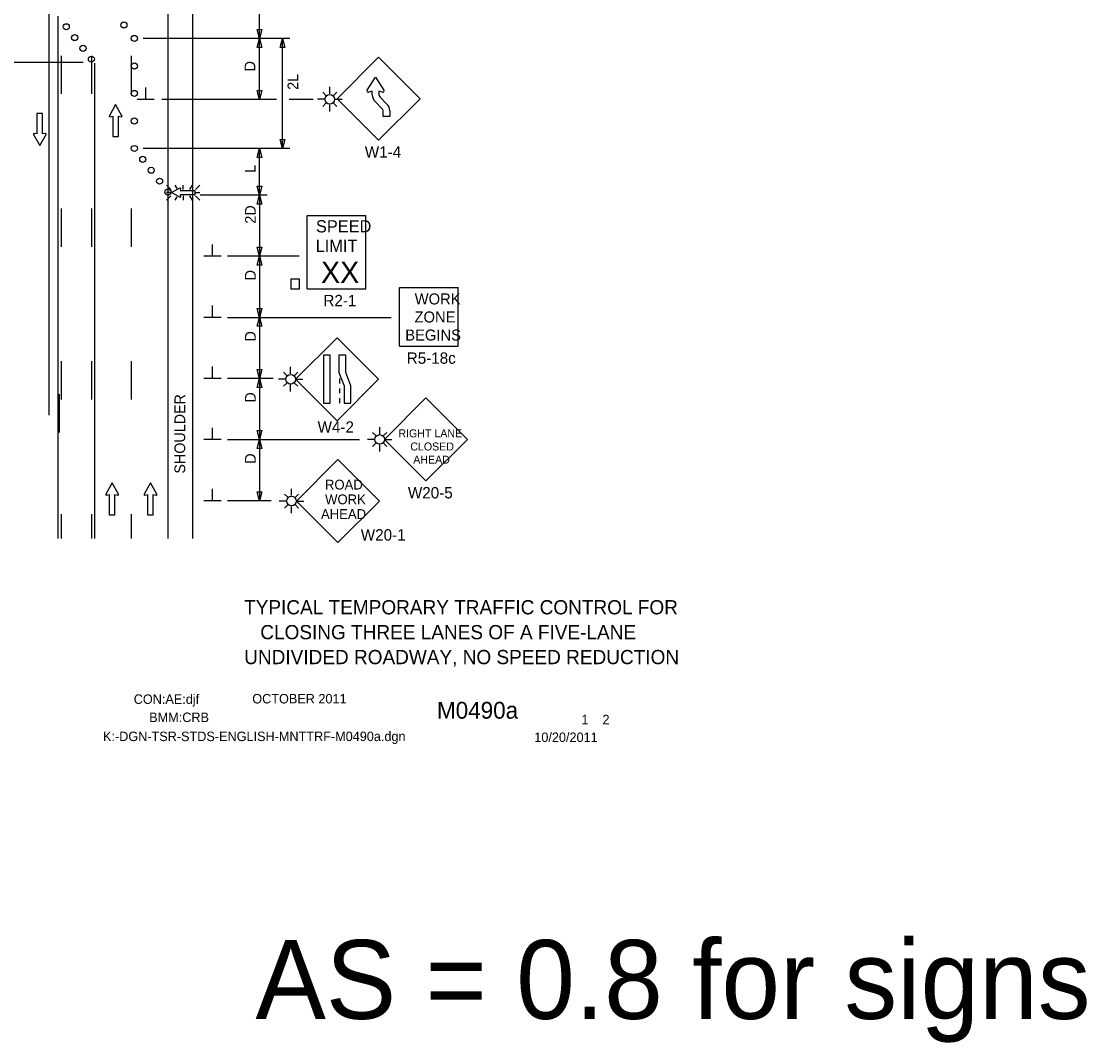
# Model space of a CAD drawing. Extents: x 16399 to 18476, y 7023 to 8321.
# Drawn here: x 17017 to 17715, y 7023 to 7691 of the extents above; entities that cross this region are included whole.
import ezdxf

# ---------------------------------------------------------------- set-up
doc = ezdxf.new("R2010")
doc.units = 0
for name, color, linetype in [('ALI_LEGAL_EX', 7, 'Continuous'), ('BORDER', 7, 'Continuous'), ('BORDER_SIGNAL_WO', 7, 'Continuous'), ('MT_SCRATCH_LEVEL_E', 7, 'Continuous'), ('PAVT_EDGE_EX', 7, 'Continuous'), ('TRAFFIC_SIGNS_PR', 7, 'Continuous'), ('TYPICAL_TEXT_DIMEN_PR', 7, 'Continuous')]:
    doc.layers.add(name, color=color, linetype=linetype)

msp = doc.modelspace()

# ---------------------------------------------------------------- linework, layer by layer
at = {"layer": 'ALI_LEGAL_EX'}
for points in [[(17043.08, 7668.47), (17043.08, 7643.47)], [(17063.08, 7668.47), (17063.08, 7643.47)], [(17089.08, 7668.47), (17089.08, 7643.47)], [(17043.08, 7568.47), (17043.08, 7543.47)], [(17063.08, 7568.47), (17063.08, 7543.47)], [(17089.08, 7568.47), (17089.08, 7543.47)], [(17043.08, 7468.47), (17043.08, 7443.47)], [(17063.08, 7468.47), (17063.08, 7443.47)], [(17089.08, 7468.47), (17089.08, 7443.47)], [(17043.08, 7368.47), (17043.08, 7352.54)], [(17063.08, 7368.47), (17063.08, 7352.54)], [(17089.08, 7368.47), (17089.08, 7352.54)]]:
    msp.add_lwpolyline(points, dxfattribs=at)
at = {"layer": 'BORDER'}
msp.add_line((17289.25, 7291.25), (17289.25, 7291.25), dxfattribs=at)
at = {"layer": 'MT_SCRATCH_LEVEL_E'}
for p, q in [((17031.01, 7630.57), (17027.26, 7630.57)), ((17027.26, 7630.57), (17027.26, 7617.31)), ((17031.01, 7630.57), (17027.26, 7630.57)), ((17027.26, 7630.57), (17027.26, 7617.31)), ((17031.01, 7617.31), (17031.01, 7630.57)), ((17031.01, 7617.31), (17031.01, 7630.57)), ((17078.82, 7636.46), (17074.71, 7629.22)), ((17078.82, 7636.46), (17074.71, 7629.22)), ((17082.97, 7629.22), (17078.82, 7636.46)), ((17082.97, 7629.22), (17078.82, 7636.46)), ((17075.19, 7628.54), (17076.97, 7628.86)), ((17075.19, 7628.54), (17076.97, 7628.86)), ((17076.97, 7628.86), (17076.97, 7615.6)), ((17076.97, 7628.86), (17076.97, 7615.6)), ((17080.71, 7615.6), (17080.71, 7628.86)), ((17080.71, 7628.86), (17082.49, 7628.54)), ((17080.71, 7615.6), (17080.71, 7628.86)), ((17080.71, 7628.86), (17082.49, 7628.54)), ((17025.01, 7616.94), (17029.15, 7609.7)), ((17025.01, 7616.94), (17029.15, 7609.7)), ((17027.26, 7617.31), (17025.49, 7617.63)), ((17027.26, 7617.31), (17025.49, 7617.63)), ((17029.15, 7609.7), (17033.27, 7616.94)), ((17029.15, 7609.7), (17033.27, 7616.94)), ((17032.78, 7617.63), (17031.01, 7617.31)), ((17032.78, 7617.63), (17031.01, 7617.31)), ((17076.97, 7615.6), (17080.71, 7615.6)), ((17076.97, 7615.6), (17080.71, 7615.6)), ((17076.52, 7388.88), (17072.41, 7381.64)), ((17076.52, 7388.88), (17072.41, 7381.64)), ((17080.67, 7381.64), (17076.52, 7388.88)), ((17080.67, 7381.64), (17076.52, 7388.88)), ((17101.61, 7388.88), (17097.5, 7381.64)), ((17101.61, 7388.88), (17097.5, 7381.64)), ((17105.75, 7381.64), (17101.61, 7388.88)), ((17105.75, 7381.64), (17101.61, 7388.88)), ((17072.89, 7380.95), (17074.67, 7381.27)), ((17072.89, 7380.95), (17074.67, 7381.27)), ((17074.67, 7381.27), (17074.67, 7368.01)), ((17074.67, 7381.27), (17074.67, 7368.01)), ((17078.41, 7368.01), (17078.41, 7381.27)), ((17078.41, 7381.27), (17080.19, 7380.95)), ((17078.41, 7368.01), (17078.41, 7381.27)), ((17078.41, 7381.27), (17080.19, 7380.95)), ((17097.98, 7380.95), (17099.76, 7381.27)), ((17097.98, 7380.95), (17099.76, 7381.27)), ((17099.76, 7381.27), (17099.76, 7368.01)), ((17099.76, 7381.27), (17099.76, 7368.01)), ((17103.5, 7368.01), (17103.5, 7381.27)), ((17103.5, 7381.27), (17105.28, 7380.95)), ((17103.5, 7368.01), (17103.5, 7381.27)), ((17103.5, 7381.27), (17105.28, 7380.95)), ((17074.67, 7368.01), (17078.41, 7368.01)), ((17074.67, 7368.01), (17078.41, 7368.01)), ((17099.76, 7368.01), (17103.5, 7368.01)), ((17099.76, 7368.01), (17103.5, 7368.01))]:
    msp.add_line(p, q, dxfattribs=at)
for centre, start, end in [((17075.11, 7629), 150.42484, 279.96381), ((17075.11, 7629), 150.42484, 279.96381), ((17082.56, 7629), 260.03619, 29.77312), ((17082.56, 7629), 260.03619, 29.77312), ((17025.42, 7617.17), 80.03619, 209.77312), ((17025.42, 7617.17), 80.03619, 209.77312), ((17032.86, 7617.17), 330.42484, 99.96381), ((17032.86, 7617.17), 330.42484, 99.96381), ((17072.81, 7381.41), 150.42484, 279.96381), ((17072.81, 7381.41), 150.42484, 279.96381), ((17080.26, 7381.42), 260.03619, 29.77312), ((17080.26, 7381.42), 260.03619, 29.77312), ((17097.9, 7381.41), 150.42484, 279.96381), ((17097.9, 7381.41), 150.42484, 279.96381), ((17105.34, 7381.42), 260.03619, 29.77312), ((17105.34, 7381.42), 260.03619, 29.77312)]:
    msp.add_arc(centre, 0.463, start, end, dxfattribs=at)
at = {"layer": 'PAVT_EDGE_EX'}
for p, q in [((17035.15, 8262.34), (17035.15, 7433.15)), ((17113.08, 8207.29), (17113.08, 7352.54)), ((17129.08, 8207.29), (17129.08, 7352.54)), ((17041.08, 7694.36), (17041.08, 7352.54)), ((17065.08, 7663.49), (17065.08, 7352.54))]:
    msp.add_line(p, q, dxfattribs=at)
msp.add_lwpolyline([(17042.08, 7421.93), (17042.08, 7446.93)], dxfattribs=at)
at = {"layer": 'TRAFFIC_SIGNS_PR'}
for p, q in [((17223.81, 7640.31), (17250.97, 7667.46)), ((17278.12, 7640.31), (17250.97, 7667.46)), ((17216.52, 7642.45), (17214.42, 7644.56)), ((17219.04, 7643.5), (17219.04, 7648)), ((17221.55, 7642.45), (17223.66, 7644.56)), ((17215.88, 7639.94), (17211.05, 7639.94)), ((17222.19, 7639.94), (17227.07, 7639.94)), ((17250.97, 7613.16), (17223.81, 7640.31)), ((17253.38, 7633.79), (17248.67, 7638.51)), ((17253.38, 7633.79), (17248.67, 7638.51)), ((17278.12, 7640.31), (17250.97, 7613.16)), ((17256.44, 7636.85), (17251.72, 7641.56)), ((17251.72, 7641.56), (17256.44, 7636.85)), ((17216.52, 7637.43), (17214.42, 7635.32)), ((17219.04, 7631.98), (17219.04, 7636.39)), ((17221.55, 7637.43), (17223.66, 7635.32)), ((17112.21, 7583.72), (17115.03, 7580.9)), ((17117.65, 7583.72), (17118.85, 7581.63)), ((17123.12, 7580.9), (17123.12, 7583.72)), ((17128.9, 7583.72), (17127.28, 7580.9)), ((17131.2, 7580.9), (17134.02, 7583.72)), ((17115.03, 7578.87), (17112.21, 7578.87)), ((17112.21, 7574.02), (17115.03, 7576.84)), ((17118.93, 7576.2), (17117.67, 7574.02)), ((17123.12, 7576.84), (17123.12, 7574.02)), ((17127.25, 7576.84), (17128.88, 7574.02)), ((17131.2, 7578.87), (17134.02, 7578.87)), ((17131.2, 7576.84), (17134.02, 7574.02)), ((17204.2, 7563.98), (17242.6, 7563.98)), ((17204.2, 7515.98), (17204.2, 7563.98)), ((17242.6, 7515.98), (17242.6, 7563.98)), ((17204.2, 7515.98), (17242.6, 7515.98)), ((17264.63, 7478.32), (17264.63, 7516.72)), ((17264.63, 7516.72), (17303.03, 7516.72)), ((17303.03, 7478.32), (17303.03, 7516.72)), ((17223.76, 7483.84), (17196.61, 7456.69)), ((17250.92, 7456.69), (17223.76, 7483.84)), ((17264.63, 7478.32), (17303.03, 7478.32)), ((17193.4, 7460.31), (17193.4, 7464.81)), ((17190.24, 7456.75), (17185.4, 7456.75)), ((17190.88, 7459.26), (17188.77, 7461.37)), ((17195.91, 7459.26), (17198.02, 7461.37)), ((17196.55, 7456.75), (17201.43, 7456.75)), ((17196.61, 7456.69), (17223.76, 7429.54)), ((17223.76, 7429.54), (17250.92, 7456.69)), ((17225.4, 7457.18), (17225.4, 7453.98)), ((17190.88, 7454.24), (17188.77, 7452.13)), ((17193.4, 7448.78), (17193.4, 7453.2)), ((17195.91, 7454.24), (17198.02, 7452.13)), ((17225.4, 7450.78), (17225.4, 7447.58)), ((17225.4, 7444.38), (17225.4, 7441.18)), ((17282.02, 7444.5), (17254.87, 7417.35)), ((17309.17, 7417.35), (17282.02, 7444.5)), ((17249.2, 7419.86), (17247.09, 7421.97)), ((17251.71, 7420.9), (17251.71, 7425.41)), ((17254.23, 7419.86), (17256.33, 7421.97)), ((17248.56, 7417.35), (17243.72, 7417.35)), ((17249.2, 7414.84), (17247.09, 7412.73)), ((17254.23, 7414.84), (17256.33, 7412.73)), ((17254.87, 7417.35), (17259.75, 7417.35)), ((17254.87, 7417.35), (17282.02, 7390.2)), ((17282.02, 7390.2), (17309.17, 7417.35)), ((17251.71, 7409.38), (17251.71, 7413.8)), ((17224.33, 7404.21), (17197.15, 7377.02)), ((17251.52, 7377.02), (17224.33, 7404.21)), ((17191.48, 7379.53), (17189.37, 7381.64)), ((17193.99, 7380.57), (17193.99, 7385.08)), ((17196.51, 7379.53), (17198.61, 7381.64)), ((17190.84, 7377.02), (17186, 7377.02)), ((17191.48, 7374.51), (17189.37, 7372.4)), ((17193.99, 7369.05), (17193.99, 7373.47)), ((17196.51, 7374.51), (17198.61, 7372.4)), ((17197.15, 7377.02), (17202.03, 7377.02)), ((17197.15, 7377.02), (17224.33, 7349.83)), ((17224.33, 7349.83), (17251.52, 7377.02))]:
    msp.add_line(p, q, dxfattribs=at)
for points in [[(17243.51, 7645.84), (17249, 7654.45), (17254.48, 7645.83)], [(17243.52, 7645.83), (17249, 7654.45), (17254.48, 7645.83)], [(17246.85, 7642.82), (17246.84, 7645.19), (17244.48, 7644.54)], [(17246.85, 7642.82), (17246.84, 7645.19), (17244.48, 7644.54)], [(17253.52, 7644.54), (17251.16, 7645.19), (17251.16, 7642.89)], [(17253.52, 7644.54), (17252.68, 7644.77), (17251.16, 7645.19), (17251.16, 7642.89)], [(17258.3, 7632.43), (17258.3, 7628.73), (17253.99, 7628.73), (17253.99, 7632.43)], [(17120.79, 7575.86), (17115.48, 7578.87), (17120.79, 7581.91)], [(17121.29, 7581.55), (17121.06, 7580.26), (17130.78, 7580.26), (17130.78, 7577.51), (17121.06, 7577.51), (17121.29, 7576.21)]]:
    msp.add_lwpolyline(points, dxfattribs=at)
for points in [[(17193.59, 7515.98), (17199.18, 7515.98), (17199.18, 7522.15), (17193.59, 7522.15)], [(17214.87, 7472.42), (17214.87, 7441.18), (17219.36, 7441.18), (17219.36, 7472.42)], [(17225, 7472.42), (17225, 7461.24), (17228.35, 7452.36), (17228.35, 7441.18), (17232.84, 7441.18), (17232.84, 7452.36), (17229.5, 7461.24), (17229.5, 7472.42)]]:
    msp.add_lwpolyline(points, close=True, dxfattribs=at)
for centre, radius in [((17046.51, 7687.37), 2), ((17084.25, 7688.6), 2), ((17052, 7680.32), 2), ((17091.1, 7679.75), 2), ((17091.1, 7679.75), 2), ((17057.49, 7673.26), 2), ((17062.97, 7666.2), 2), ((17091.1, 7661.75), 2), ((17091.1, 7643.75), 2), ((17219.04, 7639.94), 3.15), ((17091.1, 7625.75), 2), ((17091.1, 7607.75), 2), ((17096.6, 7600.62), 2), ((17102.1, 7593.49), 2), ((17107.6, 7586.36), 2), ((17113.09, 7579.24), 2), ((17193.4, 7456.75), 3.15), ((17251.71, 7417.35), 3.15), ((17193.99, 7377.02), 3.15)]:
    msp.add_circle(centre, radius, dxfattribs=at)
for centre, radius, start, end in [((17244.25, 7645.37), 0.866, 147.7292, 285.31719), ((17244.25, 7645.37), 0.866, 147.71964, 285.32011), ((17234.41, 7651.63), 10.8, 327.53351, 327.54311), ((17247.33, 7634.12), 10.8, 105.31922, 105.32004), ((17253.75, 7645.37), 0.866, 254.61481, 32.47119), ((17253.01, 7642.89), 6.17, 180.61811, 225.78746), ((17253.01, 7642.89), 6.17, 180.62445, 225.23128), ((17253.01, 7642.89), 1.85, 180, 225.78746), ((17253.01, 7642.89), 1.85, 179.8762, 225.7877), ((17252.14, 7632.43), 1.85, 0, 47.62801), ((17252.14, 7632.43), 6.17, 0, 45.78828), ((17120.95, 7581.61), 0.341, 350.04067, 118.51671), ((17120.95, 7576.15), 0.341, 241.10835, 9.26922)]:
    msp.add_arc(centre, radius, start, end, dxfattribs=at)
at = {"layer": 'TYPICAL_TEXT_DIMEN_PR'}
for p, q in [((17173.08, 7679.75), (17173.08, 7743.42)), ((17192.98, 7679.75), (17096.85, 7679.75)), ((17178.08, 7679.75), (17096.85, 7679.75)), ((17173.08, 7679.75), (17171.51, 7685.61)), ((17171.51, 7685.61), (17173.08, 7685.61)), ((17171.51, 7673.89), (17173.08, 7679.75)), ((17173.08, 7685.61), (17174.65, 7685.61)), ((17174.65, 7685.61), (17173.08, 7679.75)), ((17173.08, 7639.75), (17173.08, 7679.75)), ((17173.08, 7679.75), (17174.65, 7673.89)), ((17186.51, 7673.89), (17188.08, 7679.75)), ((17188.08, 7607.75), (17188.08, 7679.75)), ((17188.08, 7679.75), (17189.65, 7673.89)), ((17173.08, 7673.89), (17171.51, 7673.89)), ((17174.65, 7673.89), (17173.08, 7673.89)), ((17188.08, 7673.89), (17186.51, 7673.89)), ((17189.65, 7673.89), (17188.08, 7673.89)), ((16927.98, 7664.21), (17057.62, 7664.21)), ((17098.51, 7639.8), (17098.51, 7647.59)), ((17173.08, 7639.75), (17171.51, 7645.61)), ((17171.51, 7645.61), (17173.08, 7645.61)), ((17173.08, 7645.61), (17174.65, 7645.61)), ((17174.65, 7645.61), (17173.08, 7639.75)), ((17104.13, 7639.8), (17092.88, 7639.8)), ((17184.18, 7639.75), (17109.17, 7639.75)), ((17208.26, 7639.75), (17192.49, 7639.75)), ((17188.08, 7607.75), (17186.51, 7613.61)), ((17186.51, 7613.61), (17188.08, 7613.61)), ((17188.08, 7613.61), (17189.65, 7613.61)), ((17189.65, 7613.61), (17188.08, 7607.75)), ((17192.98, 7607.75), (17096.85, 7607.75)), ((17178.08, 7607.75), (17096.85, 7607.75)), ((17171.51, 7601.89), (17173.08, 7607.75)), ((17173.08, 7577.24), (17173.08, 7607.75)), ((17173.08, 7607.75), (17174.65, 7601.89)), ((17173.08, 7601.89), (17171.51, 7601.89)), ((17174.65, 7601.89), (17173.08, 7601.89)), ((17173.08, 7577.24), (17171.51, 7583.1)), ((17171.51, 7583.1), (17173.08, 7583.1)), ((17173.08, 7583.1), (17174.65, 7583.1)), ((17174.65, 7583.1), (17173.08, 7577.24)), ((17178.08, 7577.24), (17134.1, 7577.24)), ((17171.51, 7571.38), (17173.08, 7577.24)), ((17173.08, 7577.24), (17173.08, 7537.24)), ((17173.08, 7577.24), (17174.65, 7571.38)), ((17173.08, 7571.38), (17171.51, 7571.38)), ((17174.65, 7571.38), (17173.08, 7571.38)), ((17142.21, 7537.24), (17142.21, 7545.02)), ((17173.08, 7537.24), (17171.51, 7543.1)), ((17171.51, 7543.1), (17173.08, 7543.1)), ((17173.08, 7543.1), (17174.65, 7543.1)), ((17174.65, 7543.1), (17173.08, 7537.24)), ((17147.83, 7537.24), (17136.58, 7537.24)), ((17198.92, 7537.24), (17152.08, 7537.24)), ((17171.51, 7531.38), (17173.08, 7537.24)), ((17173.08, 7537.24), (17174.65, 7531.38)), ((17173.08, 7537.24), (17173.08, 7497.24)), ((17173.08, 7531.38), (17171.51, 7531.38)), ((17174.65, 7531.38), (17173.08, 7531.38)), ((17142.21, 7497.24), (17142.21, 7505.02)), ((17173.08, 7497.24), (17171.51, 7503.1)), ((17171.51, 7503.1), (17173.08, 7503.1)), ((17173.08, 7503.1), (17174.65, 7503.1)), ((17174.65, 7503.1), (17173.08, 7497.24)), ((17147.83, 7497.24), (17136.58, 7497.24)), ((17152.08, 7497.24), (17259.27, 7497.24)), ((17171.51, 7491.38), (17173.08, 7497.24)), ((17173.08, 7491.38), (17171.51, 7491.38)), ((17173.08, 7497.24), (17174.65, 7491.38)), ((17173.08, 7497.24), (17173.08, 7457.24)), ((17174.65, 7491.38), (17173.08, 7491.38)), ((17142.21, 7457.24), (17142.21, 7465.02)), ((17173.08, 7457.24), (17171.51, 7463.1)), ((17171.51, 7463.1), (17173.08, 7463.1)), ((17173.08, 7463.1), (17174.65, 7463.1)), ((17174.65, 7463.1), (17173.08, 7457.24)), ((17147.83, 7457.24), (17136.58, 7457.24)), ((17182.06, 7457.24), (17152.08, 7457.24)), ((17171.51, 7451.38), (17173.08, 7457.24)), ((17173.08, 7457.24), (17174.65, 7451.38)), ((17173.08, 7457.24), (17173.08, 7417.24)), ((17173.08, 7451.38), (17171.51, 7451.38)), ((17174.65, 7451.38), (17173.08, 7451.38)), ((17142.21, 7417.24), (17142.21, 7425.02)), ((17173.08, 7417.24), (17171.51, 7423.1)), ((17171.51, 7423.1), (17173.08, 7423.1)), ((17173.08, 7423.1), (17174.65, 7423.1)), ((17174.65, 7423.1), (17173.08, 7417.24)), ((17147.83, 7417.24), (17136.58, 7417.24)), ((17152.08, 7417.24), (17238.54, 7417.24)), ((17171.51, 7411.38), (17173.08, 7417.24)), ((17173.08, 7417.24), (17174.65, 7411.38)), ((17173.08, 7417.24), (17173.08, 7377.24)), ((17173.08, 7411.38), (17171.51, 7411.38)), ((17174.65, 7411.38), (17173.08, 7411.38)), ((17142.21, 7377.24), (17142.21, 7385.02)), ((17173.08, 7377.24), (17171.51, 7383.1)), ((17171.51, 7383.1), (17173.08, 7383.1)), ((17173.08, 7383.1), (17174.65, 7383.1)), ((17174.65, 7383.1), (17173.08, 7377.24)), ((17147.83, 7377.24), (17136.58, 7377.24)), ((17180.6, 7377.24), (17152.08, 7377.24))]:
    msp.add_line(p, q, dxfattribs=at)

# ---------------------------------------------------------------- texts
at = {"layer": 'BORDER'}
for s, p in [('TYPICAL TEMPORARY TRAFFIC CONTROL FOR', (17162.96, 7302.9)), ('CLOSING THREE LANES OF A FIVE-LANE', (17173.54, 7286.6)), ('UNDIVIDED ROADWAY, NO SPEED REDUCTION', (17163.02, 7270.3))]:
    msp.add_text(s, height=9.3, dxfattribs=at).set_placement(p)
at = {"layer": 'BORDER_SIGNAL_WO'}
for s, height, p in [('CON:AE:djf', 6.2, (17090.69, 7244.31)), ('    OCTOBER 2011    ', 6.2, (17159.08, 7244.59)), ('    M0490a   ', 11, (17272.86, 7234.63)), ('BMM:CRB   ', 6.2, (17100.81, 7232.42)), (' 1    2 ', 6.2, (17381.45, 7230.95)), ('K:-DGN-TSR-STDS-ENGLISH-MNTTRF-M0490a.dgn        ', 6.2, (17070.55, 7219.96)), ('10/20/2011    ', 6.2, (17352.93, 7219.38)), ('AS = 0.8 for signs', 51.6096, (17170.41, 7038.18))]:
    msp.add_text(s, height=height, dxfattribs=at).set_placement(p)
at = {"layer": 'TRAFFIC_SIGNS_PR'}
for s, height, p in [('W1-4', 7.44, (17241.97, 7601.72)), ('SPEED', 8, (17209.97, 7552.84)), ('LIMIT', 8, (17209.81, 7540.04)), ('XX', 14.031, (17213.31, 7519.73)), ('R2-1', 7.44, (17214.88, 7504.54)), ('WORK', 7.217, (17274.63, 7505.69)), ('ZONE', 7.217, (17274.51, 7493.88)), ('BEGINS', 7.217, (17268.44, 7482.07)), ('R5-18c', 7.44, (17269.44, 7466.88)), ('W4-2', 7.44, (17211.06, 7421.75)), ('RIGHT LANE', 5.2, (17263.94, 7418.74)), ('CLOSED', 5.2, (17271.73, 7410.14)), ('AHEAD', 5.2, (17273.68, 7401.54)), ('ROAD', 6.408, (17215.87, 7384.57)), ('WORK', 6.408, (17215.97, 7374.95)), ('W20-5', 7.44, (17270.19, 7378.76)), ('AHEAD', 6.408, (17213.28, 7365.34)), ('W20-1', 7.449, (17239.32, 7351.19))]:
    msp.add_text(s, height=height, dxfattribs=at).set_placement(p)
at = {"layer": 'TYPICAL_TEXT_DIMEN_PR'}
for s, p in [('D', (17170.28, 7658.2)), ('2L', (17198.38, 7646.14)), ('L', (17170.52, 7591.85)), ('2D', (17170.52, 7558.58)), ('D', (17170.52, 7521.46)), ('D', (17170.52, 7481.46)), ('SHOULDER', (17124.36, 7394.99)), ('D', (17170.52, 7441.46)), ('D', (17170.52, 7401.46))]:
    msp.add_text(s, height=7, rotation=90, dxfattribs=at).set_placement(p)

doc.saveas('drawing.dxf')
